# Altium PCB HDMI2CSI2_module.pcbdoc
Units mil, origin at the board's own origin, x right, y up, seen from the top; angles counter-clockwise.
Board outline 4345 x 2835 mil, 4 copper layers (Top Layer, Inner1, Inner2, Bottom Layer); 56 components, 47 nets, 282 pads, 152 vias.
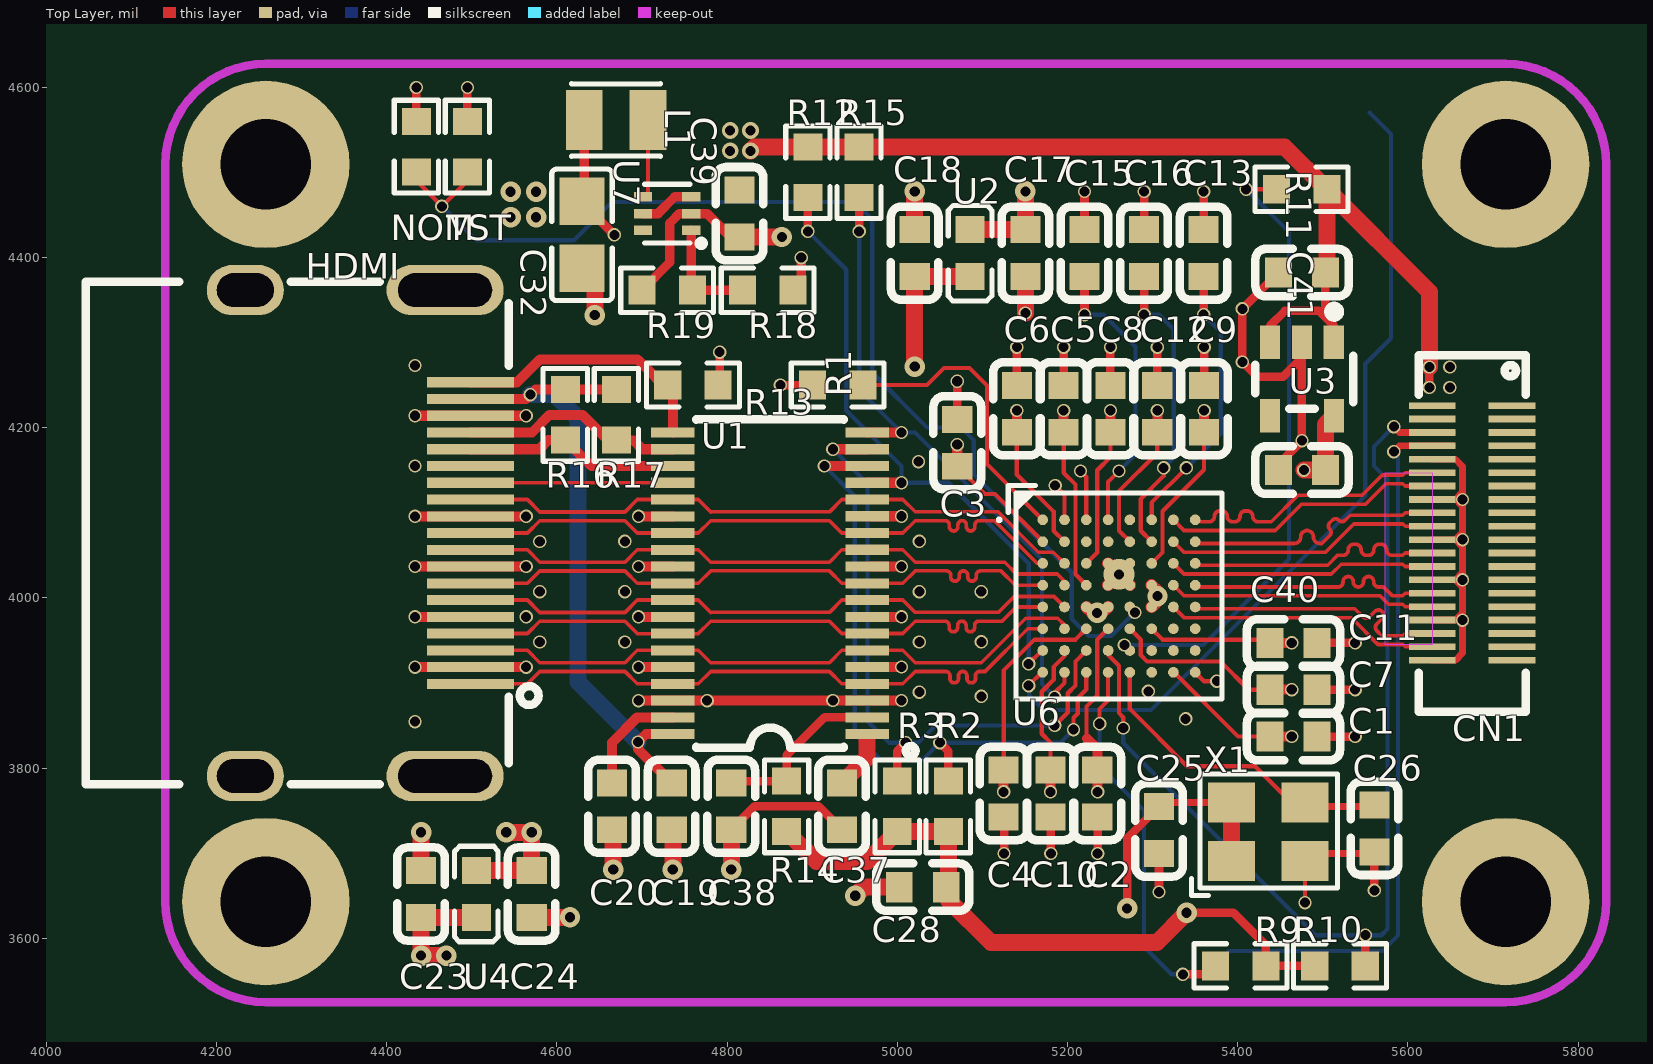
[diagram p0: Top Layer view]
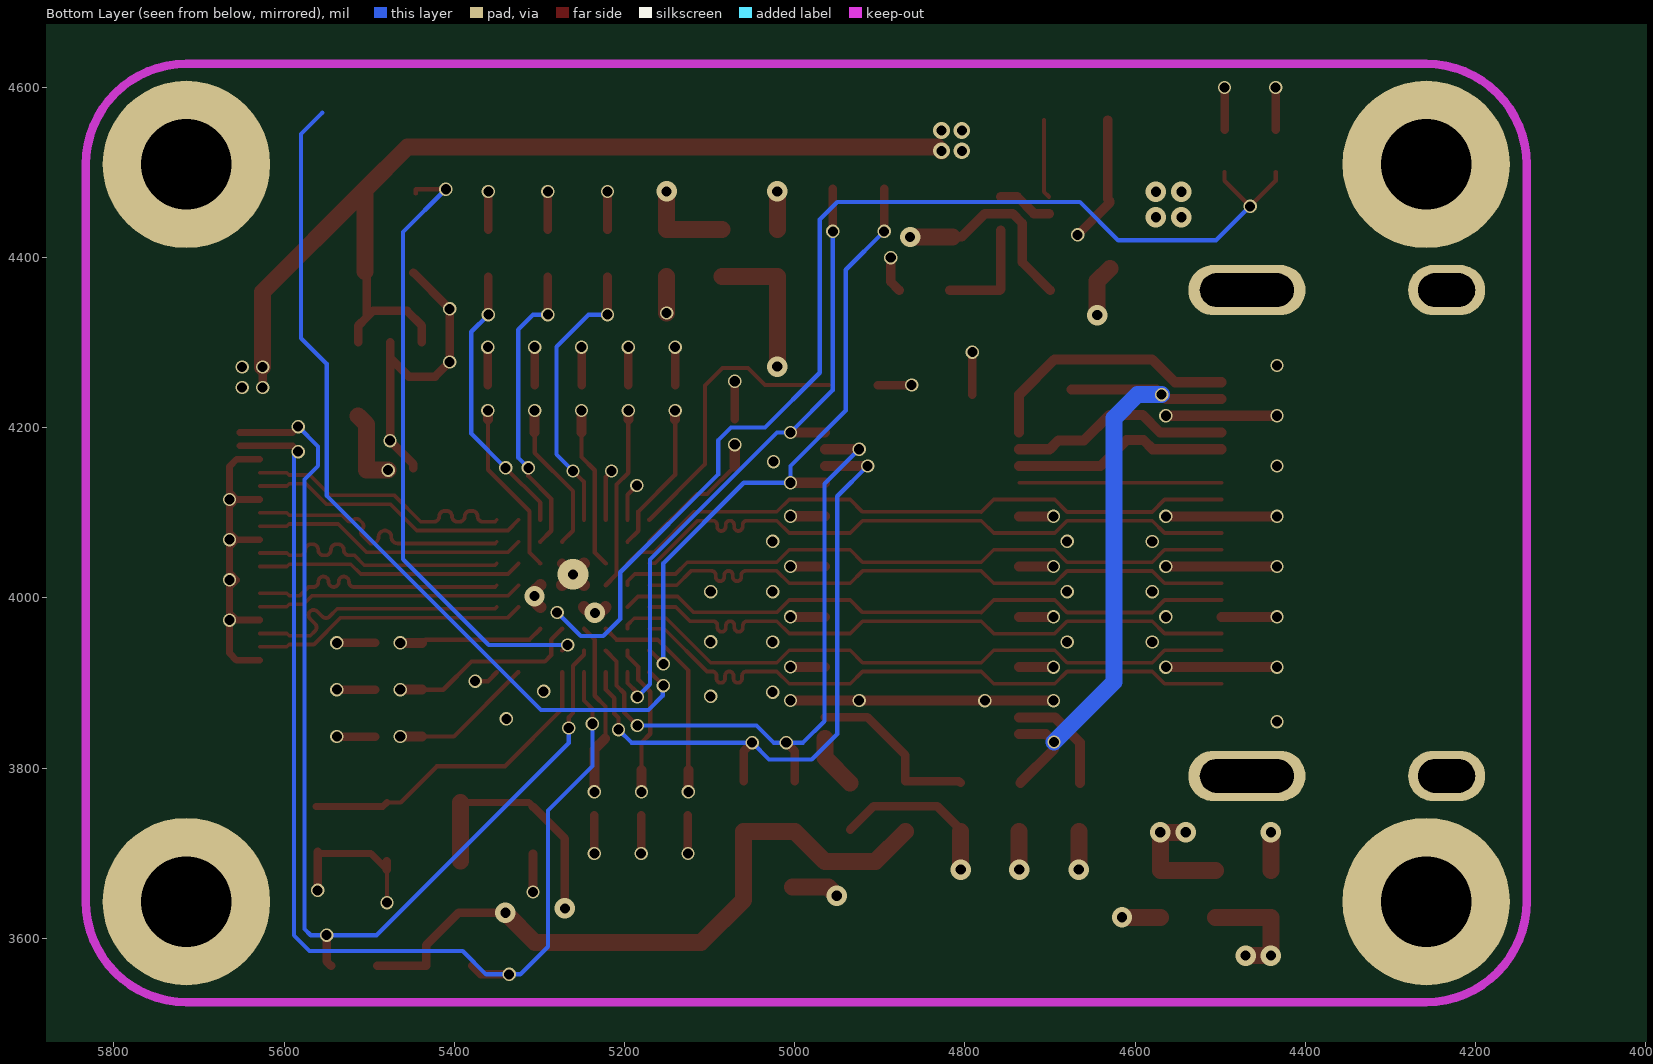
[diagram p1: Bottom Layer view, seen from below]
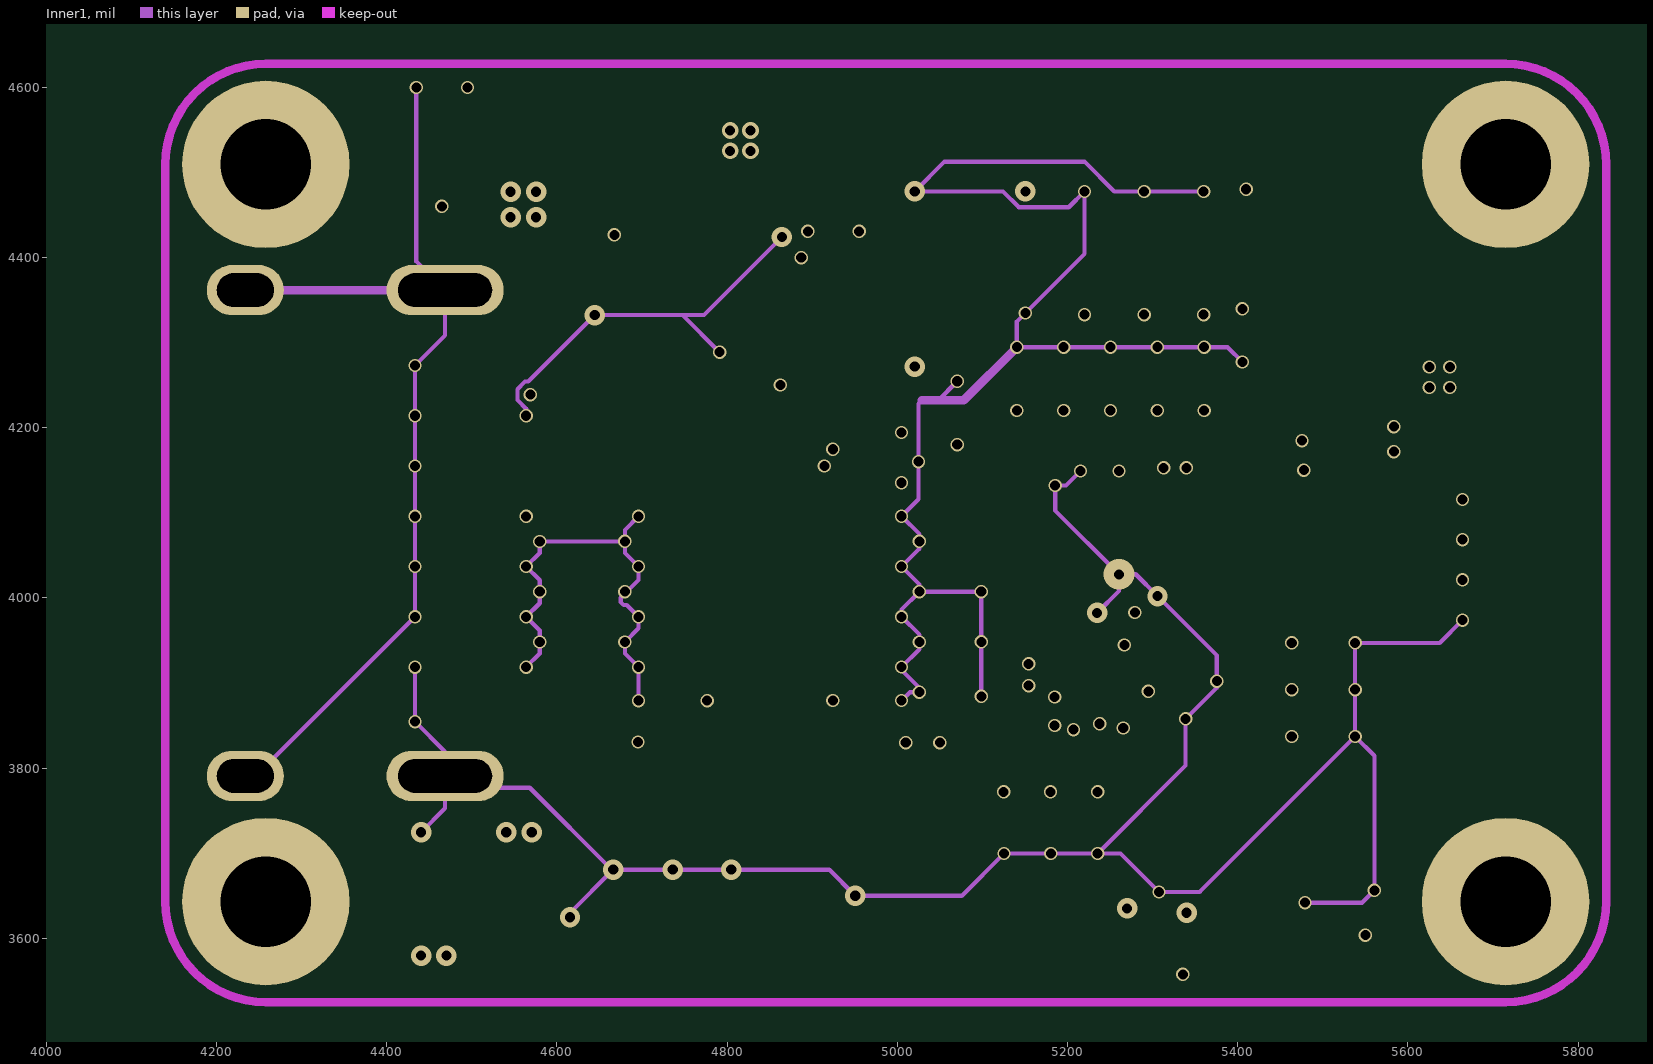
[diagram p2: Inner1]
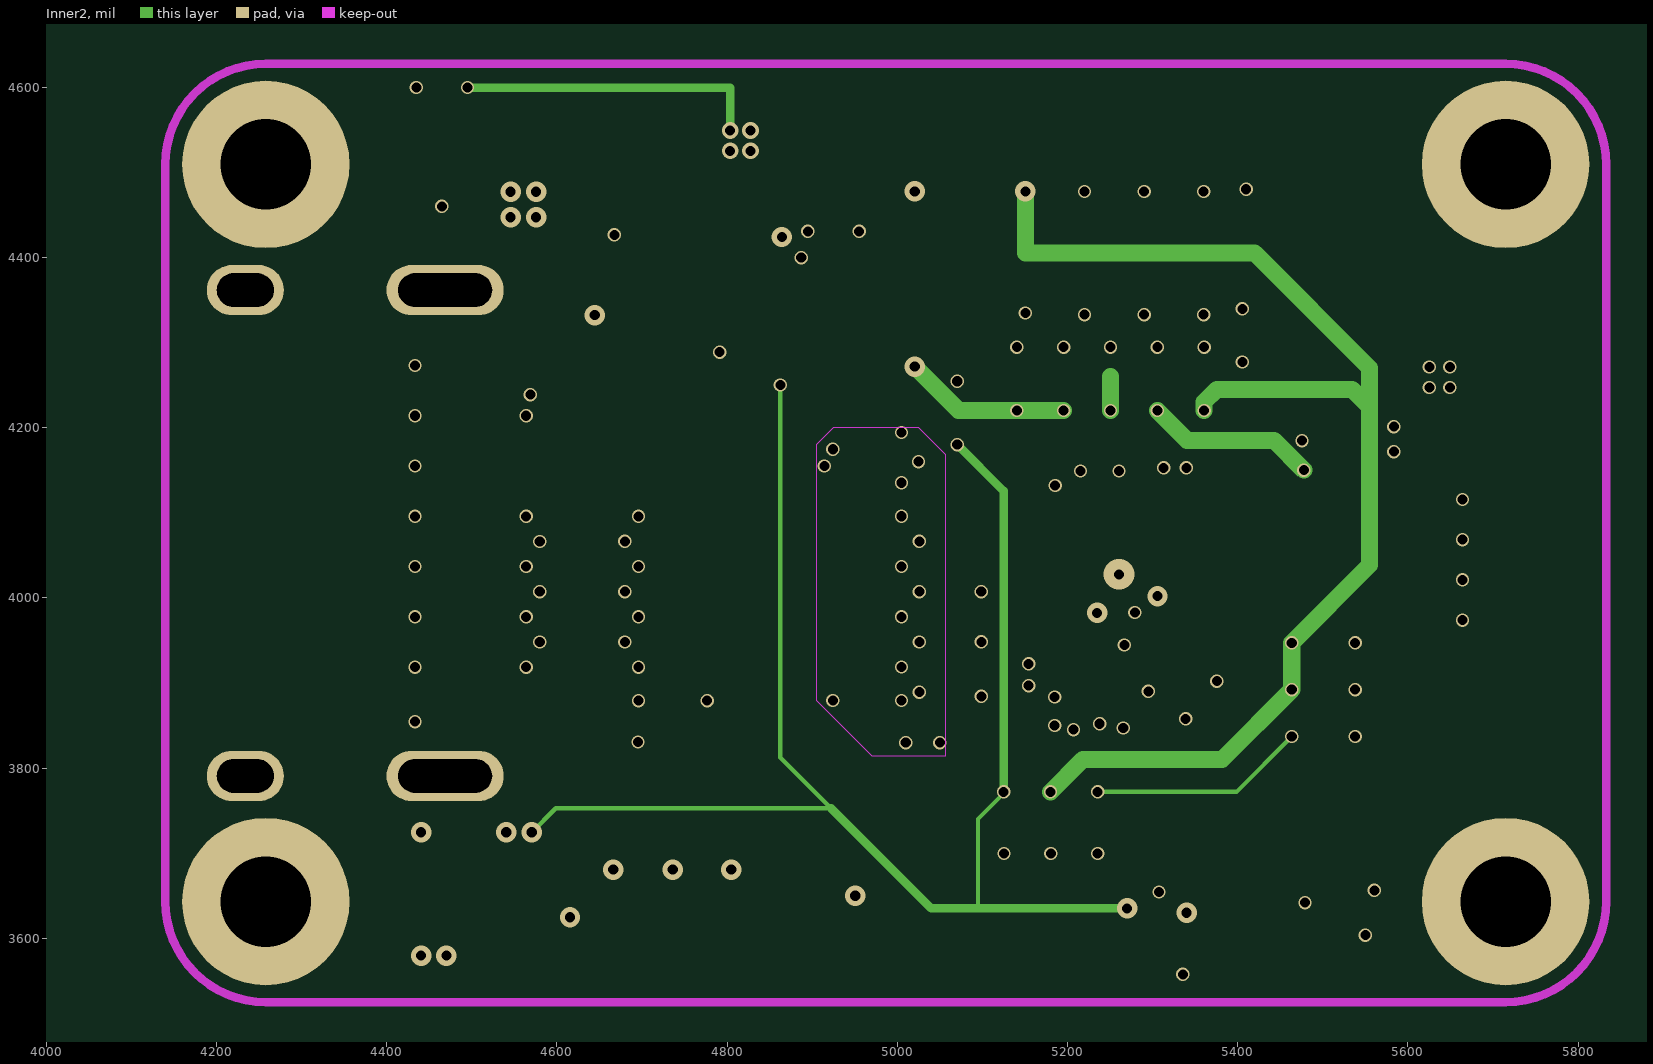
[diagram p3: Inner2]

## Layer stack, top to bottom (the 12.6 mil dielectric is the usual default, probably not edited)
Top Layer: signal copper (thickness not stored)
Dielectric: dielectric 12.6, FR-4, Dk 4.8
Inner1: signal copper (thickness not stored)
Dielectric: dielectric 12.6, FR-4, Dk 4.8
Inner2: signal copper (thickness not stored)
Dielectric: dielectric 12.6, FR-4, Dk 4.8
Bottom Layer: signal copper (thickness not stored)

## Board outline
7095,2750 2750,2750 2750,5585 7095,5585

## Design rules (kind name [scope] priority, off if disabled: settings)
BoardOutlineClearance copperThickness1oz [All] p0: genericclearance=10 ignorepadtopadclearanceinfootprint=FALSE except(0: Arc-SplitContinuation Track-SplitContinuation SMDPad-SplitContinuation THPad-SplitContinuation Via-SplitContinuation Fill-SplitContinuation Poly-SplitContinuation Region-SplitContinuation Text-SplitContinuation; 6: SMDPad-CutoutEdge THPad-CutoutEdge Via-CutoutEdge Fill-CutoutEdge Region-CutoutEdge; 11.8: Track-OutlineEdge SMDPad-OutlineEdge THPad-OutlineEdge Via-OutlineEdge Fill-OutlineEdge Region-OutlineEdge Poly-OutlineEdge Text-OutlineEdge Track-CutoutEdge)
BoardOutlineClearance copperThickness2oz [All] p0: genericclearance=10 ignorepadtopadclearanceinfootprint=FALSE except(0: Arc-SplitContinuation Track-SplitContinuation SMDPad-SplitContinuation THPad-SplitContinuation Via-SplitContinuation Fill-SplitContinuation Poly-SplitContinuation Region-SplitContinuation Text-SplitContinuation; 6: SMDPad-CutoutEdge THPad-CutoutEdge Via-CutoutEdge Fill-CutoutEdge Region-CutoutEdge; 11.8: Track-OutlineEdge SMDPad-OutlineEdge THPad-OutlineEdge Via-OutlineEdge Fill-OutlineEdge Region-OutlineEdge Poly-OutlineEdge Text-OutlineEdge Track-CutoutEdge)
BoardOutlineClearance copperThicknessInner0.5oz [All] p0: genericclearance=10 ignorepadtopadclearanceinfootprint=FALSE except(0: Arc-SplitContinuation Track-SplitContinuation SMDPad-SplitContinuation THPad-SplitContinuation Via-SplitContinuation Fill-SplitContinuation Poly-SplitContinuation Region-SplitContinuation Text-SplitContinuation; 6: SMDPad-CutoutEdge THPad-CutoutEdge Via-CutoutEdge Fill-CutoutEdge Region-CutoutEdge; 11.8: Track-OutlineEdge SMDPad-OutlineEdge THPad-OutlineEdge Via-OutlineEdge Fill-OutlineEdge Region-OutlineEdge Poly-OutlineEdge Text-OutlineEdge Track-CutoutEdge)
Clearance copperThickness1oz [(InNet('$1N490') OR InNet('$1N473') OR InNet('$1N491') OR InNet('3V3') OR InNet('1V2') OR InNet('2V5') OR InNet('GND') OR InNet('$1N487') OR InNet('$1N3181') OR InNet('A3V3') OR InNet('A1V2') OR InNet('HDMISDA') OR InNet('HDMISCL') OR InNet('HDMI2+') OR InNet('HDMI2-') OR InNet('HDMI1+') OR InNet('HDMI1-') OR InNet('HDMI0+') OR InNet('HDMI0-') OR InNet('HDMICLK+') OR InNet('HDMICLK-') OR InNet('HDMIHPD') OR InNet('HOST_SDA') OR InNet('HOST_SCL') OR InNet('HDMI5V') OR InNet('HDMICEC') OR InNet('$1N13322') OR InNet('CSID3P') OR InNet('CSID2P') OR InNet('CSICN') OR InNet('CSID1P') OR InNet('CSID0P') OR InNet('CSICP') OR InNet('CSID3N') OR InNet('CSID2N') OR InNet('CSID1N') OR InNet('CSID0N') OR InNet('HDMIHPD_OUT') OR InNet('HDMICEC_OUT') OR InNet('$1N17500') OR InNet('HDMISCL_OUT') OR InNet('HDMISDA_OUT') OR InNet('$1N18101') OR InNet('$1N18201') OR InNet('$1N17874') OR InNet('$1N34238') OR InNet('$1N34236'))] p1: gap=7 ignorepadtopadclearanceinfootprint=FALSE except(4: Track-Track Track-SMDPad SMDPad-SMDPad Track-Via SMDPad-Via THPad-Via Via-Via; 6: Track-THPad SMDPad-THPad THPad-THPad Track-Fill SMDPad-Fill THPad-Fill Via-Fill Fill-Fill SMDPad-Region THPad-Region Via-Region Fill-Region Region-Region Track-Poly SMDPad-Poly THPad-Poly Via-Poly Fill-Poly Poly-Poly Track-Text SMDPad-Text THPad-Text Via-Text Fill-Text Region-Text Poly-Text Text-Text; 6.9: Track-Hole SMDPad-Hole THPad-Hole Via-Hole Fill-Hole Region-Hole Poly-Hole Text-Hole Sheet-Hole; 11.8: Track-Region Region-Poly Track-Sheet SMDPad-Sheet THPad-Sheet Via-Sheet Fill-Sheet Region-Sheet Poly-Sheet Text-Sheet)
Clearance copperThickness2oz [All] p1: gap=7 ignorepadtopadclearanceinfootprint=FALSE except(6: Track-SMDPad SMDPad-SMDPad Track-THPad SMDPad-THPad THPad-THPad Track-Via SMDPad-Via THPad-Via Via-Via Track-Fill SMDPad-Fill THPad-Fill Via-Fill Fill-Fill SMDPad-Region THPad-Region Via-Region Fill-Region Region-Region Track-Poly SMDPad-Poly THPad-Poly Via-Poly Fill-Poly Poly-Poly Track-Text SMDPad-Text THPad-Text Via-Text Fill-Text Region-Text Poly-Text Text-Text; 6.9: Track-Hole SMDPad-Hole THPad-Hole Via-Hole Fill-Hole Region-Hole Poly-Hole Text-Hole Sheet-Hole; 8: Track-Track; 11.8: Track-Region Region-Poly Track-Sheet SMDPad-Sheet THPad-Sheet Via-Sheet Fill-Sheet Region-Sheet Poly-Sheet Text-Sheet)
Clearance copperThicknessInner0.5oz [All] p1: gap=7 ignorepadtopadclearanceinfootprint=FALSE except(3.5: Track-Track; 6: Track-SMDPad SMDPad-SMDPad Track-THPad SMDPad-THPad THPad-THPad Track-Via SMDPad-Via THPad-Via Via-Via Track-Fill SMDPad-Fill THPad-Fill Via-Fill Fill-Fill SMDPad-Region THPad-Region Via-Region Fill-Region Region-Region Track-Poly SMDPad-Poly THPad-Poly Via-Poly Fill-Poly Poly-Poly Track-Text SMDPad-Text THPad-Text Via-Text Fill-Text Region-Text Poly-Text Text-Text; 6.9: Track-Hole SMDPad-Hole THPad-Hole Via-Hole Fill-Hole Region-Hole Poly-Hole Text-Hole Sheet-Hole; 11.8: Track-Region Region-Poly Track-Sheet SMDPad-Sheet THPad-Sheet Via-Sheet Fill-Sheet Region-Sheet Poly-Sheet Text-Sheet)
DiffPairsRouting differentialPair [All] p1: maxuncoupledlength=10 minlimit=6 maxlimit=6 mostfreqgap=6 toplayer_minwidth=4.3 toplayer_prefwidth=4.3 toplayer_maxwidth=100 bottomlayer_minwidth=4.3 bottomlayer_prefwidth=4.3 bottomlayer_maxwidth=100 midlayer1_minwidth=4.3 midlayer1_prefwidth=4.3 midlayer1_maxwidth=100 midlayer2_minwidth=4.3 midlayer2_prefwidth=4.3 midlayer2_maxwidth=100
PasteMaskExpansion pasteMaskExpansion [All] p1: expansion=0
PlaneConnect innerPlane [All] p1: planeconnectstyle=Relief reliefexpansion=20 reliefentries=4 reliefconductorwidth=10 reliefairgap=10
PolygonConnect copperRegion [All] p1: connectstyle=Direct reliefentries=4 reliefconductorwidth=10 polygonreliefangle="90 Angle" airgapwidth=10
RoutingVias viaSize [All] p1: viastyle="Through Hole" holewidth=12 minholewidth=7.9 maxholewidth=248 width=24 minwidth=11.8 maxwidth=393.7
SolderMaskExpansion solderMaskExpansion [All] p1: useseparateexpansions=TRUE expansion=2 expansionbottom=2
Width copperThickness1oz [All] p1: maxlimit=100 minlimit=4 preferedwidth=10
Width copperThickness2oz [All] p1: maxlimit=100 minlimit=8 preferedwidth=10
Width copperThickness0.5oz [All] p1: maxlimit=100 minlimit=4 preferedwidth=10

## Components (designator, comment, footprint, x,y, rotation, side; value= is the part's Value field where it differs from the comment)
C1 "CGA0603X7R104K500JT" C0603 5465.5,3837 r180 top
C2 "CGA0603X7R104K500JT" C0603 5235,3770 r90 top
C3 "CGA0603X7R104K500JT" C0603 5070.5,4182 r270 top
C4 "CGA0603X7R104K500JT" C0603 5125,3770 r90 top
C5 "CGA0603X7R104K500JT" C0603 5195.5,4222 r270 top
C6 "CGA0603X7R104K500JT" C0603 5140.5,4222 r270 top
C7 "CGA0603X7R104K500JT" C0603 5465.5,3892 r180 top
C8 "CGA0603X7R104K500JT" C0603 5250.5,4222 r270 top
C9 "CGA0603X7R104K500JT" C0603 5360.5,4222 r270 top
C10 "CGA0603X7R104K500JT" C0603 5180,3770 r90 top
C11 "CGA0603X7R104K500JT" C0603 5465.5,3947 r180 top
C12 "CGA0603X7R104K500JT" C0603 5305.5,4222 r270 top
C13 "CGA0603X7R104K500JT" C0603 5360,4405 r90 top
C15 "CGA0603X7R104K500JT" C0603 5220,4405 r90 top
C16 "CGA0603X7R104K500JT" C0603 5290,4405 r90 top
C17 "CL10A105KB8NNNC" C0603 5150.5,4405 r90 top
C18 "CGA0603X7R104K500JT" C0603 5020.5,4405 r270 top
C19 "CGA0603X7R104K500JT" C0603 4735,3755 r90 top
C20 "CGA0603X7R104K500JT" C0603 4665,3755 r90 top
C23 "CL10A105KB8NNNC" C0603 4440.5,3652 r270 top
C24 "CGA0603X7R104K500JT" C0603 4570.5,3652 r90 top
C25 "CGA0603X7R104K500JT" C0603 5307.53,3727.09 r90 top
C26 "CL10C150JB8NNNC" C0603 5560.59,3729.03 r90 top
C28 "CGA0603X7R104K500JT" C0603 5030,3660 r0 top
C32 "CL21A226MAQNNNE" C0805 4629.61,4426.42 r90 top
C37 "CGA0603X7R104K500JT" C0603 4935,3755 r90 top
C38 "CGA0603X7R104K500JT" C0603 4805,3755 r90 top
C39 "CL10A105KB8NNNC" C0603 4814.61,4451.42 r90 top
C40 "CL10A105KB8NNNC" C0603 5475.5,4150 r0 top
C41 "CL10A105KB8NNNC" C0603 5475.5,4382 r0 top
CN1 "DF40C-40DS-0.4V(51)" CONN-SMD_DF40C-40DS-0.4V51 5675.43,4076.18 r90 top
HDMI "HDMI-001S" HDMI-SMD_HDMI-001S 4366.38,4076.08 r270 top
L1 "WPN252012H1R0MT" IND-SMD_L2.5-W2.0_WPN252012H 4669.61,4561.42 r180 top
NOM "0603WAF1002T5E" R0603 4435,4530 r90 top
R1 "0603WAF2001T5E" R0603 4930,4250 r180 top
R2 "0603WAF4702T5E" R0603 5060,3755 r90 top
R3 "0603WAF4702T5E" R0603 5000,3755 r90 top
R9 "0603WAF4701T5E" R0603 5403.38,3567.57 r180 top
R10 "0603WAF4701T5E" R0603 5520.18,3567.57 r0 top
R11 "0603WAF1002T5E" R0603 5475,4480 r180 top
R12 "0603WAF4702T5E" R0603 4895,4500 r270 top
R13 "0603WAF1002T5E" R0603 4760,4250 r180 top
R14 "0603WAF1002T5E" R0603 4870,3755 r270 top
R15 "0603WAF1003T5E" R0603 4955,4500 r270 top
R16 "M55342H12B1E70PT5" R0603 4610,4215 r270 top
R17 "M55342H12B1E70PT5" R0603 4670,4215 r270 top
R18 "Res_0603" R0603 4847.7,4361.43 r0 top
R19 "Res_0603" R0603 4729.61,4361.42 r0 top
TST "0603WAF1002T5E" R0603 4495,4530 r270 top
U1 "TPD12S521DBTR" TSSOP-38_L9.7-W4.4-P0.50-LS6.4-BL 4850.5,4017 r90 top
U2 "BLM18EG221SN1D" L0603 5085.5,4405 r270 top
U3 "TLV75725PDBVR" SOT-23-5_L2.9-W1.6-P0.95-LS2.8-BR 5475.5,4257 r90 top
U4 "BLM18EG221SN1D" L0603 4505.5,3652 r90 top
U6 "TC358743XBG" BGA-64_L6.0-W6.0-W8-R8-P0.65-D0.40-TL 5260.5,4002 r0 top
U7 "TLV62568ADRLR" SOT-563_L1.6-W1.2-P0.50-LS1.6-BL 4729.61,4451.42 r90 top
X1 "OT2EL4C4JI-111OLP-27M" OSC-SMD_4P-L3.2-W2.5-BL 5435.8,3725.15 r0 top

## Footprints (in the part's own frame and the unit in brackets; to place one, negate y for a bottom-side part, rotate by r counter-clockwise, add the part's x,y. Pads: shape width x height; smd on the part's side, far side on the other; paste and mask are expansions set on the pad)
BGA-64_L6.0-W6.0-W8-R8-P0.65-D0.40-TL [mm]
  round 0.32 smd: A1(-2.275,2.275) A2(-1.625,2.275) A3(-0.975,2.275) A4(-0.325,2.275) A5(0.325,2.275) A6(0.975,2.275) A7(1.625,2.275) A8(2.275,2.275) B1(-2.275,1.625) B2(-1.625,1.625) B3(-0.975,1.625) B4(-0.325,1.625) B5(0.325,1.625) B6(0.975,1.625) B7(1.625,1.625) B8(2.275,1.625) C1(-2.275,0.975) C2(-1.625,0.975) C3(-0.975,0.975) C4(-0.325,0.975) C5(0.325,0.975) C6(0.975,0.975) C7(1.625,0.975) C8(2.275,0.975) D1(-2.275,0.325) D2(-1.625,0.325) D3(-0.975,0.325) D4(-0.325,0.325) D5(0.325,0.325) D6(0.975,0.325) D7(1.625,0.325) D8(2.275,0.325) E1(-2.275,-0.325) E2(-1.625,-0.325) E3(-0.975,-0.325) E4(-0.325,-0.325) E5(0.325,-0.325) E6(0.975,-0.325) E7(1.625,-0.325) E8(2.275,-0.325) F1(-2.275,-0.975) F2(-1.625,-0.975) F3(-0.975,-0.975) F4(-0.325,-0.975) F5(0.325,-0.975) F6(0.975,-0.975) F7(1.625,-0.975) F8(2.275,-0.975) G1(-2.275,-1.625) G2(-1.625,-1.625) G3(-0.975,-1.625) G4(-0.325,-1.625) G5(0.325,-1.625) G6(0.975,-1.625) G7(1.625,-1.625) G8(2.275,-1.625) H1(-2.275,-2.275) H2(-1.625,-2.275) H3(-0.975,-2.275) H4(-0.325,-2.275) H5(0.325,-2.275) H6(0.975,-2.275) H7(1.625,-2.275) H8(2.275,-2.275)
  silkscreen extent -3.63,-3.08 3.08,3.3
C0603 [mm]
  rect 0.8x0.9 smd: 1(-0.7,0) 2(0.7,0)
  silkscreen extent -1.39,-0.71 1.39,0.71
C0805 [mm]
  rect 1.41x1.35 smd: 1(-1,0) 2(1,0)
  silkscreen extent -1.96,-0.9 1.96,0.9
CONN-SMD_DF40C-40DS-0.4V51 [mm]
  rect 0.2x1.4 smd: 1(3.8,-1.19) 2(3.8,1.19) 3(3.4,-1.19) 4(3.4,1.19) 5(3,-1.19) 6(3,1.19) 7(2.6,-1.19) 8(2.6,1.19) 9(2.2,-1.19) 10(2.2,1.19) 11(1.8,-1.19) 12(1.8,1.19) 13(1.4,-1.19) 14(1.4,1.19) 15(1,-1.19) 16(1,1.19) 17(0.6,-1.19) 18(0.6,1.19) 19(0.2,-1.19) 20(0.2,1.19) 21(-0.2,-1.19) 22(-0.2,1.19) 23(-0.6,-1.19) 24(-0.6,1.19) 25(-1,-1.19) 26(-1,1.19) 27(-1.4,-1.19) 28(-1.4,1.19) 29(-1.8,-1.19) 30(-1.8,1.19) 31(-2.2,-1.19) 32(-2.2,1.19) 33(-2.6,-1.19) 34(-2.6,1.19) 35(-3,-1.19) 36(-3,1.19) 37(-3.4,-1.19) 38(-3.4,1.19) 39(-3.8,-1.19) 40(-3.8,1.19)
  silkscreen extent -5.33,-1.6 5.3,1.6
HDMI-SMD_HDMI-001S [mm]
  rect 0.3x2.6 smd: 1(4.5,3.36) 2(4,3.36) 3(3.5,3.36) 4(3,3.36) 5(2.5,3.36) 6(2,3.36) 7(1.5,3.36) 8(1,3.36) 9(0.5,3.36) 10(0,3.36) 11(-0.5,3.36) 12(-1,3.36) 13(-1.5,3.36) 14(-2,3.36) 15(-2.5,3.36) 16(-3,3.36) 17(-3.5,3.36) 18(-4,3.36) 19(-4.5,3.36)
  oval 1.5x3.5 hole 1 slot 2.8 at 90 deg: 20(-7.25,2.6) 21(7.25,2.6)
  oval 1.5x2.3 hole 1 slot 1.7 at 90 deg: 22(-7.25,-3.36) 23(7.25,-3.36)
  silkscreen extent -7.5,-8.12 7.5,5.39
IND-SMD_L2.5-W2.0_WPN252012H [mm]
  rect 1.1x1.8 smd: 1(-0.95,0) 2(0.95,0)
  silkscreen extent -1.33,-1.09 1.33,1.09
L0603 [mm]
  rect 0.8x0.864 smd: 1(-0.7,0) 2(0.7,0)
  silkscreen extent -1.42,-0.65 1.42,0.65
OSC-SMD_4P-L3.2-W2.5-BL [mm]
  rect 1.4x1.2 smd: 1(-1.1,-0.875) 2(1.1,-0.875) 3(1.1,0.875) 4(-1.1,0.875)
  silkscreen extent -2.29,-1.9 2.07,1.72
R0603 [mil]
  rect 31.75x34.02 smd: 1(-29.66,0) 2(29.66,0)
  silkscreen extent -55,-26 55,26
SOT-23-5_L2.9-W1.6-P0.95-LS2.8-BR [mm]
  rect 1x0.6 smd: 1(1.1,-0.95) 2(1.1,0) 3(1.1,0.95) 4(-1.1,0.95) 5(-1.1,-0.95)
  silkscreen extent -0.89,-1.52 2.16,1.4
SOT-563_L1.6-W1.2-P0.50-LS1.6-BL [mm]
  rect 0.28x0.545 smd: 1(-0.5,-0.723) 2(0,-0.723) 3(0.5,-0.723) 4(0.5,0.723) 5(0,0.723) 6(-0.5,0.723)
  silkscreen extent -0.99,-1.12 0.88,0.68
TSSOP-38_L9.7-W4.4-P0.50-LS6.4-BL [mm]
  rect 0.3x1.3 smd: 1(-4.501,-2.899) 2(-3.999,-2.901) 3(-3.498,-2.901) 4(-2.999,-2.901) 5(-2.499,-2.901) 6(-1.999,-2.901) 7(-1.499,-2.901) 8(-0.999,-2.901) 9(-0.499,-2.901) 10(0.001,-2.901) 11(0.501,-2.901) 12(1.001,-2.901) 13(1.501,-2.901) 14(2.001,-2.901) 15(2.501,-2.901) 16(3.001,-2.901) 17(3.501,-2.901) 18(4.001,-2.901) 19(4.501,-2.901) 20(4.5,2.899) 21(4.001,2.9) 22(3.501,2.899) 23(3.002,2.899) 24(2.499,2.901) 25(2,2.9) 26(1.5,2.9) 27(1,2.9) 28(0.5,2.9) 29(0,2.9) 30(-0.5,2.9) 31(-1,2.9) 32(-1.5,2.9) 33(-2,2.9) 34(-2.5,2.9) 35(-3,2.9) 36(-3.5,2.9) 37(-4,2.9) 38(-4.5,2.9)
  silkscreen extent -5.14,-4.34 4.9,2.2

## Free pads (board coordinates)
  round 196.85 hole 106.3: 1(4258.11,3643.11) 1(4258.11,4509.25) 1(5714.8,3643.11) 1(5714.8,4509.25)

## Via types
v1: diameter 15.7, hole 11.8, Top Layer to Bottom Layer, 124 vias
v2: diameter 24, hole 12, Top Layer to Bottom Layer, 21 vias
v3: diameter 19.7, hole 11.8, Top Layer to Bottom Layer, 4 vias
v4: diameter 24, hole 11.8, Top Layer to Bottom Layer, 2 vias
v5: diameter 36, hole 11.8, Top Layer to Bottom Layer, 1 vias

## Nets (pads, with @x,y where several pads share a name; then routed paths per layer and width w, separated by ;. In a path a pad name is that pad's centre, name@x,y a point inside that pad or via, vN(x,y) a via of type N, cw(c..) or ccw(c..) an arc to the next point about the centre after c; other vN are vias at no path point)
1V2: C7.2 C8.2 C9.2 C10.2 C11.2 C17.2 C32.2 L1.2 R18.2 U2.1 U6.C3 U6.C6 U6.F5 U6.F6 U6.G2 | length 2825
  Top Layer w5: C10.2 5180,3830 5169.69,3840.31 5169.69,3889.69 5183.73,3903.73 5183.73,3918.73 5196.52,3931.52 U6.G2 ; U6.C3 5234.91,4053.19 5234.91,4149.91 5250.5,4165.5 C8.2 ; U6.F5 5286.09,3950.82 5286.09,3932.72 5293.59,3925.22 5379.77,3925.23 5413,3892 C7.2 ; U6.F6 5311.68,3950.82 5434.12,3950.82 C11.2 ; U6.C6 5311.69,4053.19 5311.69,4101.69 5360.5,4150.5 C9.2@5360.5,4209.44
  Top Layer w11: L1.2 4632.21,4468.39 C32.2 4629.61,4464.38 v1(4667.57,4426.42) ; R18.2 4887.2,4371.27 v1(4887.2,4399.55)
  Top Layer w11.8: v1(5180,3772) C10.2 ; C8.2 v1(5250.5,4220) ; C9.2@5360.5,4209.44 v1(5360.5,4220) ; C7.2 v1(5463.5,3892) ; C11.2 v1(5463.5,3947)
  Top Layer w20: U2.1 C17.2 v2(5150.51,4477.42)
  Inner2 w20: v2(5150.51,4477.42) 5150.51,4405 5420,4405 5555,4270 5555,4224.14 ; v1(5180,3772) 5218,3810 5381.5,3810 v1(5463.5,3892) v1(5463.5,3947) 5555,4038.5 5555,4224.14 ; v1(5250.5,4220) 5250.5,4260 ; v1(5360.5,4220) 5360.5,4230 5375.5,4245 5534.14,4245 5555,4224.14
  other v2: 4545.7,4447.13 4575.7,4447.13 4545.7,4477.13 4575.7,4477.13
2V5: C12.2 C40.2 U3.5 U6.B5 | length 472.4
  Top Layer w5: U6.B5 5260.5,4078.78 5260.5,4125.27 5305.5,4170.27 C12.2
  Top Layer w11.8: C12.2 v1(5305.5,4220)
  Top Layer w20: v1(5477.69,4149.88) 5502.94,4149.88 C40.2 5503.06,4203.84 U3.5
  Inner2 w20: v1(5305.5,4220) 5340.5,4185 5442.57,4185 v1(5477.69,4149.88)
3V3: C1.2 C2.2 C23.2 C28.2 C39.2 C41.2 CN1.2 CN1.4 R2.1 R3.1 R9.1 R10.1 R11.1 R12.1 R14.2 R15.1 TST.1 U3.1 U3.3 U4.1 U6.F4 U6.H7 U7.3 U7.5 | length 3312.2
  Top Layer w5: 5222.4,3835.1 5222.4,3872.4 5234.9,3884.9 5234.9,3950.81 U6.F4 ; U6.H7 5325.07,3912.43 5400.5,3837 C1.2
  Top Layer w10: TST.1@4495,4549.69 v1(4495,4599.53) ; v2(5340,3630) 5395,3630 5433.04,3591.96 R9.1 R10.1 ; U3.3 5438.11,4319.61 5455.5,4337 5495.5,4337 5503.06,4329.44 ; C41.2@5504.66,4383.6 C41.2 5503.06,4329.44 ; U3.1 5512.9,4319.6 5503.06,4329.44 ; v1(5625.24,4247.14) v1(5625.24,4271.14)
  Top Layer w11: U7.5 4718.98,4451.41 4738.67,4471.1 U7.3
  Top Layer w11.8: 5223.02,3834.48 5235.5,3822 v1(5235.5,3772) ; C1.2 v1(5463.5,3837)
  Top Layer w20: v2(4440.49,3579.58) v2(4470.35,3579.57) ; v2(4440.49,3579.58) C23.2 U4.1 ; v3(4827.7,4525.13) 4832.23,4529.66 R12.1 R15.1 5455,4529.66 R11.1 ; R14.2 4905.34,3690 4964.66,3690 R3.1 R2.1 5060,3645 5110,3595 5305,3595 v2(5340,3630) ; C41.2@5504.66,4383.6 R11.1 ; v1(5625.24,4271.14) 5625.24,4359.42 R11.1
  Inner2 w5: v1(5235.5,3772) 5398.5,3772 v1(5463.5,3837)
  Inner2 w10: v1(4495,4599.53) 4803.7,4599.53 v3(4803.7,4549.13)
  other v1: 5649.24,4247.14 5649.24,4271.14
  other v3: 4803.7,4525.13 4827.7,4549.13
$1N473: C16.1 U6.B6 | length 357.6
  Top Layer w5: U6.B6 5286.09,4078.78 5286.09,4116.09 5312.97,4142.97 v1(5312.97,4152.66)
  Top Layer w10: v1(5289.99,4332.58) C16.1
  Bottom Layer w5: v1(5289.99,4332.58) 5307.42,4332.58 5325,4315 5325,4164.69 v1(5312.97,4152.66)
$1N487: R1.1 U6.A1 | length 347.6
  Top Layer w5: R1.1 5035,4250 5055,4270 5085,4270 5105.5,4249.5 5105.5,4157 U6.A1
$1N490: C13.1 U6.A6 | length 327.7
  Top Layer w5: U6.A6 5298.89,4111.8 v1(5339.74,4152.66)
  Top Layer w10: v1(5359.99,4332.58) C13.1
  Bottom Layer w5: v1(5339.74,4152.66) 5380,4192.91 5380,4312.57 v1(5359.99,4332.58)
$1N491: C15.1 U6.A4 | length 337.2
  Top Layer w5: U6.A4 5247.7,4136.24 v1(5260.5,4149.05)
  Top Layer w10: v1(5219.99,4332.58) C15.1
  Bottom Layer w5: v1(5219.99,4332.58) 5242.42,4332.58 5280,4295 5280,4168.54 v1(5260.5,4149.05)
$1N3181: NOM.1 TST.2 U6.E5 | length 1338.7
  Top Layer w5: NOM.1 4435,4490 v1(4465,4460) 4495,4490 TST.2
  Bottom Layer w5: v1(4465,4460) 4505,4420 4620,4420 4665,4465 4950,4465 4970.58,4444.42 4970.58,4264.42 5035,4200 5075,4200 5090,4185 5090,4145 5205,4030 5205,3975 5225,3955 5251.39,3955 v1(5279.1,3982.71)
$1N13322: C26.2 U6.H5 X1.3 | length 379.9
  Top Layer w5: U6.H5 5273.3,3869.2 5340.5,3802 5420.5,3802 5462.9,3759.6 X1.3
  Top Layer w8: X1.3 5484.05,3754.65 C26.2@5562.53,3754.65
$1N17500: C20.2 U1.37 | length 131
  Top Layer w11.8: C20.2 4665,3830 4694.52,3859.53 U1.37
$1N17874: R11.2 U6.G5 | length 740
  Top Layer w5: v1(5266.8,3944.51) U6.G5 ; v1(5410,4480) 5445,4480 5445.34,4479.66 R11.2@5445.34,4475
  Bottom Layer w5: v1(5266.8,3944.51) 5359.51,3944.51 5460.21,4045.21 5460.21,4429.79 v1(5410,4480)
$1N18101: C37.2 U1.1 | length 64.6
  Top Layer w20: C37.2 4964.59,3812.15 U1.1@4964.59,3834.94
$1N18201: C38.2 R14.1 U1.2 | length 209.4
  Top Layer w10: C38.2 4807.1,3784.66 R14.1 4870,3815 4914.56,3859.57 U1.2
$1N34236: R18.1 R19.2 U7.1 | length 129.6
  Top Layer w11: U7.1 4758.06,4362.64 R19.2 R18.1
$1N34238: L1.1 U7.4 | length 92.7
  Top Layer w5: U7.4 4707.01,4476.95 L1.1
A1V2: C5.2 C6.2 C18.2 U2.2 U6.B2 U6.D3 | length 760.6
  Top Layer w5: C6.2@5140.5,4209.44 5140.5,4144.5 5183.72,4101.28 5183.72,4078.78 U6.B2 ; C5.2@5195.5,4209.44 5195.5,4147 5209.32,4133.18 5209.32,4027.59 U6.D3
  Top Layer w11.8: C6.2@5140.5,4209.44 v1(5140.5,4220) ; C5.2@5195.5,4209.44 v1(5195.5,4220)
  Top Layer w20: v2(5020.5,4271.66) C18.2 U2.2
  Inner2 w20: v2(5020.5,4271.66) 5072.16,4220 v1(5140.5,4220) v1(5195.5,4220)
A3V3: C3.2 C4.2 C24.2 C25.2 R1.2 U4.2 U6.B1 U6.F3 X1.1 X1.4 | length 2753.5
  Top Layer w5: C3.2 5102.94,4122 5114.91,4122 U6.B1 ; C4.2 5125,3914.68 5161.14,3950.82 5209.32,3950.82 U6.F3
  Top Layer w8: C25.2 5312.47,3759.6 X1.4
  Top Layer w10: v1(4862.59,4250) R1.2@4902.44,4250 ; v2(5270,3635) 5270,3717.12 C25.2
  Top Layer w11.8: C3.2 v1(5070.5,4180) ; v1(5125,3772) C4.2
  Top Layer w20: U4.2 C24.2 v2(4570.51,3724.42) ; v2(4540.65,3724.43) v2(4570.51,3724.42) ; X1.1 X1.4
  Inner2 w5: v2(4570.51,3724.42) 4598.81,3752.72 4922.28,3752.72 4862.59,3812.41 v1(4862.59,4250) ; 5094.62,3635 5095,3635.38 5095,3740 v1@5125,3770
  Inner2 w10: 4922.28,3752.72 5040,3635 5094.62,3635 v2(5270,3635) ; v1(5070.5,4180) 5125,4125.5 v1(5125,3772)
CSICN: CN1.26 U6.C7 | length 315.2
  Top Layer w4.3: U6.C7 5336.93,4027.94 5509.94,4027.94 5521.53,4039.53 5594,4039.53 5596.72,4036.81 CN1.26
CSICP: CN1.24 U6.C8 | length 315.4
  Top Layer w4.3: U6.C8 5352.22,4038.24 5505.67,4038.24 5517.27,4049.83 5523.35,4049.83 ccw(c5523.35,4056.42) 5529.93,4056.42 cw(c5536.52,4056.42) 5536.52,4063 5538.35,4063 cw(c5538.35,4056.42) 5544.93,4056.42 ccw(c5551.52,4056.42) 5551.52,4049.83 5553.35,4049.83 ccw(c5553.35,4056.42) 5559.93,4056.42 cw(c5566.52,4056.42) 5566.52,4063 5568.35,4063 cw(c5568.35,4056.42) 5574.93,4056.42 ccw(c5581.52,4056.42) 5581.52,4049.83 5594,4049.83 5596.72,4052.56 CN1.24
CSID0N: CN1.38 U6.E7 | length 323.5
  Top Layer w4.3: U6.E7 5336.93,3976.75 5533.25,3976.75 5564.95,3945.05 5594,3945.05 5596.72,3942.33 CN1.38
CSID0P: CN1.36 U6.E8 | length 324.3
  Top Layer w4.3: U6.E8 5352.22,3987.05 5537.52,3987.05 5546.57,3978 ccw(c5550.81,3982.24) 5555.05,3978 5561.05,3983.99 cw(c5565.29,3979.75) 5569.53,3975.5 5563.54,3969.51 ccw(c5567.78,3965.27) 5563.54,3961.03 5569.22,3955.35 5594,3955.35 5596.72,3958.07 CN1.36
CSID1N: CN1.32 U6.D7 | length 314.6
  Top Layer w4.3: U6.D7 5336.93,4002.35 5567.09,4002.35 5577.14,3992.29 5594,3992.29 5596.72,3989.57 CN1.32
CSID1P: CN1.30 U6.D8 | length 313.3
  Top Layer w4.3: U6.D8 5352.22,4012.65 5517.74,4012.65 ccw(c5517.74,4018.65) 5523.74,4018.65 5523.74,4018.95 cw(c5529.74,4018.95) 5535.74,4018.95 5535.74,4018.65 ccw(c5541.74,4018.65) 5547.74,4018.65 5547.74,4018.95 cw(c5553.74,4018.95) 5559.74,4018.95 5559.74,4018.65 ccw(c5565.74,4018.65) 5565.74,4012.65 5571.35,4012.65 5581.41,4002.59 5594,4002.59 5596.72,4005.32 CN1.30
CSID2N: CN1.20 U6.B7 | length 324.2
  Top Layer w4.3: U6.B7 5336.93,4053.53 5503.1,4053.53 5536.35,4086.78 5594,4086.78 5596.72,4084.06 CN1.20
CSID2P: CN1.18 U6.B8 | length 323.9
  Top Layer w4.3: U6.B8 5352.22,4063.83 5466.51,4063.83 ccw(c5466.51,4071.33) 5474.01,4071.33 5474.01,4071.5 cw(c5481.51,4071.5) 5489.01,4071.5 5489.01,4071.33 ccw(c5496.51,4071.33) 5496.51,4063.83 5498.83,4063.83 5508.08,4073.08 ccw(c5504.33,4076.83) 5508.08,4080.58 cw(c5511.83,4084.33) 5508.08,4088.08 5511.19,4091.19 cw(c5514.94,4087.44) 5518.69,4091.19 ccw(c5522.44,4094.94) 5526.19,4091.19 5532.08,4097.08 5594,4097.08 5596.72,4099.81 CN1.18
CSID3N: CN1.14 U6.A7 | length 333.1
  Top Layer w4.3: U6.A7 5336.93,4079.12 5444.12,4079.12 5475,4110 5550.15,4110 5574.17,4134.02 5594,4134.02 5596.72,4131.3 CN1.14
CSID3P: CN1.12 U6.A8 | length 332
  Top Layer w4.3: U6.A8 5352.22,4089.42 5366.4,4089.42 ccw(c5366.4,4095.71) 5372.69,4095.71 cw(c5378.98,4095.71) 5378.98,4102 5381.4,4102 cw(c5381.4,4095.71) 5387.69,4095.71 ccw(c5393.98,4095.71) 5393.98,4089.42 5396.4,4089.42 ccw(c5396.4,4095.71) 5402.69,4095.71 cw(c5408.98,4095.71) 5408.98,4102 5411.4,4102 cw(c5411.4,4095.71) 5417.69,4095.71 ccw(c5423.98,4095.71) 5423.98,4089.42 5439.42,4089.42 5470.3,4120.3 5545.88,4120.3 5569.9,4144.32 5594,4144.32 5596.72,4147.05 CN1.12
GND: C1.1 C2.1 C3.1 C4.1 C5.1 C6.1 C7.1 C8.1 C9.1 C10.1 C11.1 C12.1 C13.2 C15.2 C16.2 C17.1 C18.1 C19.1 C20.1 C23.1 C24.1 C25.1 C26.1 C28.1 C32.1 C37.1 C38.1 C39.1 C40.1 C41.1 CN1.10 CN1.16 CN1.22 CN1.28 CN1.34 CN1.40 HDMI.2 HDMI.5 HDMI.8 HDMI.11 HDMI.17 HDMI.20 HDMI.21 HDMI.22 HDMI.23 NOM.2 R13.1 R19.1 U1.3 U1.5 U1.8 U1.11 U1.14 U1.25 U1.28 U1.31 U1.34 U1.36 U3.2 U6.A2 U6.A3 U6.C4 U6.C5 U6.D4 U6.D5 U6.D6 U6.E3 U6.E4 U6.E6 U6.H8 U7.2 X1.2 | length 10873.4
  Top Layer w5: v1(5185.5,4132) 5196.52,4120.98 U6.A2 ; v1(5215.21,4148.92) 5222.11,4142.03 U6.A3 ; U6.H8 5360.5,3902 v1(5375.5,3902) ; v1(5479.11,3641.76) X1.2@5479.11,3680.6
  Top Layer w8: X1.2@5479.11,3680.6 5498.04,3699.53 C26.1@5560.59,3699.53 ; CN1.40 5655.64,3926.58 5664.14,3935.08 v1(5664.14,3973.81) ; CN1.34 5655.64,3973.81 5664.14,3982.31 5664.14,4012.56 5655.64,4021.06 5664.14,4029.56 5664.14,4059.81 CN1.22@5655.65,4068.3 ; CN1.22 CN1.22@5655.64,4068.31 ; CN1.16 5655.64,4115.55 5664.14,4124.05 5664.14,4154.3 5655.64,4162.8 CN1.10 ; v1@5659.89,4111.3 5664.14,4107.05 5664.14,4076.8 CN1.22@5655.65,4068.3
  Top Layer w10: NOM.2@4435,4549.69 v1(4435,4599.53) ; R13.1@4791.3,4238.68 v1(4791.3,4288.53) ; C38.1 4832.56,3755 4907.44,3755 C37.1 ; C3.1 v1(5070.5,4254.41) ; v1(5125.49,3699.58) C4.1@5125.5,3744.44 ; C6.1 v1(5140.51,4294.42) ; v1(5180.49,3699.58) C10.1@5180.5,3744.44 ; C5.1 v1(5195.51,4294.42) ; C15.2 v1(5220.01,4477.43) ; v1(5235.49,3699.58) C2.1@5235.5,3744.44 ; C8.1 v1(5250.51,4294.42) ; C16.2 v1(5290.01,4477.43) ; C12.1 v1(5305.51,4294.42) ; v1(5307.52,3654.37) C25.1 ; C13.2 v1(5360.01,4477.42) ; C9.1 v1(5360.51,4294.42) ; C40.1@5447.94,4152 5447.94,4157 v1(5475.51,4184.56) U3.2@5475.51,4282.01 ; C41.1 v1(5405.5,4339.55) v1(5405.5,4277) 5422.57,4259.93 5453.43,4259.93 U3.2@5475.51,4282.01 ; U3.2 U3.2@5475.51,4282.01 ; X1.2@5479.11,3680.6 X1.2 ; C1.1 v1(5537.92,3836.99) ; C7.1 v1(5537.92,3891.99) ; C11.1 v1(5537.92,3946.99) ; v1(5560.58,3656.31) 5560.59,3699.53 C26.1
  Top Layer w11: R19.1 4732.7,4394.17 4732.7,4440.13 4743.98,4451.41 U7.2 4776.42,4451.41 4803.97,4423.86 C39.1
  Top Layer w11.8: v1(4433.34,3918.6) HDMI.2 v1(4563.98,3918.6) ; v1(4433.34,3977.65) HDMI.5 ; v1(4433.34,4036.71) HDMI.8 v1(4563.98,4036.71) ; v1(4433.34,4095.76) HDMI.11 v1(4563.98,4095.76) ; v1(4433.34,4213.88) HDMI.17 v1(4563.98,4213.88) ; v1(4696.01,3879.22) U1.36 v1(4776.66,3879.22) v1@4924.33,3879.22 ; v1(4696.01,3918.59) U1.34 ; v1(4696.01,3977.64) U1.31 ; v1(4696.01,4036.7) U1.28 ; v1(4696.01,4095.74) U1.25 ; v1(4924.39,3879.28) U1.3 v1(5005.04,3879.28) ; U1.5 v1(5005.04,3918.62) ; U1.8 v1(5005.04,3977.68) ; U1.11 v1(5005.04,4036.74) ; U1.14 v1(5005.04,4095.78) ; v5(5260.5,4027.6) U6.C5
  Top Layer w14: U6.E3 5228.96,3982.35 v4(5234.9,3982.35) 5240.85,3982.35 U6.E4 ; U6.D4 v5(5260.5,4027.6) ; U6.C4 v5(5260.5,4027.6) ; U6.D5 v5(5260.5,4027.6) ; U6.E6 5305.74,3996.05 v4(5305.74,4002) 5305.74,4007.95 U6.D6
  Top Layer w20: C23.1 v2(4440.51,3724.42) ; C24.1 4570.64,3624.58 v2(4615.49,3624.58) ; C32.1 4644.61,4372.05 v2(4644.61,4332.2) ; v2(4666.29,3680.61) C20.1@4666.3,3725.47 ; v2(4736.29,3680.61) C19.1@4736.3,3725.47 ; v2(4804.99,3680.61) C38.1@4805,3725.47 ; C39.1 v2(4864.46,4423.86) ; v2(4950.62,3650) 4960.62,3660 C28.1 ; C18.1 v2(5020.51,4477.42) ; v1(5150.5,4334.59) C17.1
  Inner1 w5: HDMI.23 4246.33,3790.64 v1(4433.34,3977.65) v1(4433.34,4036.71) v1(4433.34,4095.76) v1(4433.34,4154.82) v1(4433.34,4213.88) v1(4433.34,4272.93) 4468.74,4308.33 HDMI.20 4435,4395.26 v1(4435,4599.53) ; v1(4433.34,3918.6) v1(4433.34,3854.54) 4468.74,3819.14 HDMI.21 ; v2(4440.51,3724.42) 4468.74,3752.65 HDMI.21 ; v1(4563.98,3918.6) 4579.98,3934.6 v1(4579.98,3948.1) 4579.98,3961.66 v1(4563.98,3977.65) 4579.98,3993.65 v1(4579.98,4007.15) 4579.98,4020.71 v1(4563.98,4036.71) 4579.98,4052.71 v1(4579.98,4066.21) v1(4680.02,4066.25) ; v1(4563.98,4213.88) 4563.98,4222.06 4553.68,4232.36 4553.68,4245.04 4562.65,4254 4566.41,4254 v2(4644.61,4332.2) 4747.63,4332.2 ; v2(4615.49,3624.58) 4615.49,3629.81 v2(4666.29,3680.61) ; v1(4696.01,3879.22) v1(4696.01,3918.59) 4680.02,3934.58 v1(4680.02,3948.14) 4696.01,3964.14 v1(4696.01,3977.64) 4682.18,3991.46 4678.54,3991.46 4675,3995 4675,4000 4696.01,4021.01 v1(4696.01,4036.7) 4680.02,4052.69 v1(4680.02,4066.25) 4680.02,4079.75 v1(4696.01,4095.74) ; v1(4791.3,4288.53) 4747.63,4332.2 ; v2(4864.46,4423.86) 4772.8,4332.2 4747.63,4332.2 ; v1(5005.04,3879.28) 5014.83,3889.07 v1(5026.03,3889.07) ; v1@5025.98,3894.02 5005.04,3914.96 v1(5005.04,3918.62) 5026.03,3939.62 v1(5026.03,3948.12) 5026.03,3956.68 v1(5005.04,3977.68) 5005.04,3986.18 v1(5026.03,4007.18) ; 5029,4232 5025,4228 v1(5025,4160) 5025,4115.75 v1(5005.04,4095.78) 5026.03,4074.79 v1(5026.03,4066.23) 5026.03,4057.73 v1(5005.04,4036.74) 5026.03,4015.74 v1(5026.03,4007.18) ; 5048.09,4232 v1(5070.5,4254.41) ; v1(5098.7,4007.22) v1(5026.03,4007.18) ; v1(5098.72,3884.11) v1(5098.72,3948.16) v1(5098.7,4007.22) ; v1(5215.21,4148.92) 5198.29,4132 v1(5185.5,4132) 5185.5,4102.6 v5(5260.5,4027.6) ; v4(5234.9,3982.35) 5260.5,4007.95 v5(5260.5,4027.6) ; v1(5360.01,4477.42) v1(5290.01,4477.43) 5255.01,4477.43 5220.01,4512.43 5055.52,4512.43 v2(5020.51,4477.42) 5124.35,4477.42 5142.85,4458.92 5201.51,4458.92 v1(5220.01,4477.43) 5220.01,4404.1 v1(5150.5,4334.59) 5140.51,4324.6 v1(5140.51,4294.42) v1(5195.51,4294.42) v1(5250.51,4294.42) v1(5305.51,4294.42) v1(5360.51,4294.42) 5388.08,4294.42 v1(5405.5,4277) ; v1(5479.11,3641.76) 5546.03,3641.76 v1(5560.58,3656.31) 5560.58,3814.33 v1(5537.92,3836.99) ; v1(5664.14,3973.81) 5637.33,3946.99 v1(5537.92,3946.99) v1(5537.92,3891.99) v1(5537.92,3836.99) ; HDMI.21 4482.54,3776.85 4568.15,3776.85 4664.39,3680.61 v2(4666.29,3680.61) ; v2(4666.29,3680.61) v2(4736.29,3680.61) v2(4804.99,3680.61) 4920.01,3680.61 v2(4950.62,3650) 5075.91,3650 v1(5125.49,3699.58) v1(5180.49,3699.58) v1(5235.49,3699.58) ; v1(5235.49,3699.58) 5262.32,3699.58 v1(5307.52,3654.37) 5355.31,3654.37 v1(5537.92,3836.99) ; v1(5235.49,3699.58) 5338.8,3802.89 v1(5338.8,3857.74) 5375.5,3894.44 v1(5375.5,3902) 5375.5,3932.24 v4(5305.74,4002) 5280.14,4027.6 v5(5260.5,4027.6)
  Inner1 w10: HDMI.22 HDMI.20 ; 5029,4232 5048.09,4232 5078.09,4232 v1(5140.51,4294.42)
  other v1: 5295,3890 4680.02,4007.2 5664.14,4021.06 5664.14,4068.3 5664.14,4115.55
HDMI0+: HDMI.7 U1.10 U1.29 U6.D1 | length 740.5
  Top Layer w4.3: HDMI.7 4565.44,4017.02 4579.96,4031.54 4680.03,4031.54 4694.56,4017.01 U1.29 4766.23,4017.01 4780.76,4031.54 4920.29,4031.58 4934.82,4017.05 U1.10 5006.49,4017.05 5021.02,4031.58 5057.77,4031.58 cw(c5057.77,4026.58) 5062.77,4026.58 5062.77,4024.5 ccw(c5067.77,4024.5) 5072.77,4024.5 5072.77,4026.58 cw(c5077.77,4026.58) 5082.77,4026.58 5082.77,4024.5 ccw(c5087.77,4024.5) 5092.77,4024.5 5092.77,4026.58 cw(c5097.77,4026.58) 5097.77,4031.58 5121.91,4031.58 5138.69,4014.8 U6.D1
HDMI0-: HDMI.9 U1.12 U1.27 U6.D2 | length 741.8
  Top Layer w4.3: HDMI.9 4565.44,4056.39 4580,4041.84 4680.02,4041.84 4694.55,4056.38 U1.27 ; U1.27 4766.23,4056.38 4780.76,4041.84 4920.29,4041.88 4934.82,4056.41 U1.12 5006.5,4056.41 5021.03,4041.88 5126.18,4041.88 5140.07,4027.98 5187.89,4027.98 5196.52,4019.36 U6.D2
HDMI1+: HDMI.4 U1.7 U1.32 U6.E1 | length 742.2
  Top Layer w4.3: HDMI.4 4565.44,3957.96 4579.96,3972.48 4680.03,3972.48 4694.56,3957.95 4736.34,3957.95 4766.23,3957.95 4780.76,3972.48 4920.29,3972.52 4934.82,3957.99 U1.7 5006.5,3957.99 5021.03,3972.53 5055.89,3972.53 cw(c5055.89,3967.53) 5060.89,3967.53 5060.89,3965 ccw(c5065.89,3965) 5070.89,3965 5070.89,3967.53 cw(c5075.89,3967.53) 5080.89,3967.53 5080.89,3965 ccw(c5085.89,3965) 5090.89,3965 5090.89,3967.53 cw(c5095.89,3967.53) 5095.89,3972.53 5123.04,3972.53 5139.71,3989.2 U6.E1
HDMI1-: HDMI.6 U1.9 U1.30 U6.E2 | length 740.9
  Top Layer w4.3: HDMI.6 4565.44,3997.33 4580,3982.78 4680.02,3982.78 4694.55,3997.32 U1.30 4766.23,3997.32 4780.76,3982.78 4920.29,3982.82 4934.82,3997.36 U1.9 5006.49,3997.36 5021.02,3982.83 5118.77,3982.83 5137.55,4001.61 5184.11,4001.61 U6.E2
HDMI2+: HDMI.1 U1.4 U1.35 U6.F1 | length 759.8
  Top Layer w4.3: HDMI.1 4565.44,3898.91 4579.96,3913.43 4680.03,3913.43 4694.56,3898.89 U1.35 4766.23,3898.89 4780.76,3913.43 4920.29,3913.47 4934.82,3898.93 U1.4 5006.49,3898.93 5021.02,3913.47 5056.91,3913.47 cw(c5056.91,3908.47) 5061.91,3908.47 5061.91,3905 ccw(c5066.91,3905) 5071.91,3905 5071.91,3908.47 cw(c5076.91,3908.47) 5081.91,3908.47 5081.91,3905 ccw(c5086.91,3905) 5091.91,3905 5091.91,3908.47 cw(c5096.91,3908.47) 5096.91,3913.47 5103.04,3913.47 5153.18,3963.61 U6.F1
HDMI2-: HDMI.3 U1.6 U1.33 U6.F2 | length 757.4
  Top Layer w4.3: HDMI.3 4565.44,3938.28 4580,3923.73 4680.02,3923.73 4694.55,3938.26 U1.33 4766.23,3938.26 4780.76,3923.73 4920.29,3923.77 4934.82,3938.3 U1.6 5006.5,3938.3 5021.03,3923.77 5098.77,3923.77 5151.02,3976.02 5188.67,3976.02 5196.52,3968.17 U6.F2
HDMI5V: C19.2 HDMI.18 R16.1 R17.1 U1.38 | length 767.1
  Top Layer w11.8: HDMI.18 4563.85,4233.56 v1(4568.98,4238.7) 4574.94,4244.66 R16.1 R17.1@4675,4244.66 ; C19.2 4695.44,3822.12 v1(4695.44,3830.56) 4704.73,3839.84 U1.38
  Bottom Layer w20: v1(4568.98,4238.7) 4597.27,4238.7 4625,4210.97 4625,3901 v1(4695.44,3830.56)
HDMICEC: R12.2 U1.16 U6.G1 | length 760.8
  Top Layer w5: v1(5154.39,3922.43) 5169.98,3938.02 U6.G1
  Top Layer w10: v1(4895,4430.47) R12.2@4895,4480.31
  Top Layer w11.8: U1.16 v1(5005.04,4135.15)
  Bottom Layer w5: v1(4895,4430.47) 4940,4385.46 4940,4220 5005.04,4154.96 v1(5005.04,4135.15) 5059.85,4135.15 5154.39,4040.61 v1(5154.39,3922.43)
HDMICEC_OUT: HDMI.13 U1.23 | length 237.6
  Top Layer w4.3: HDMI.13 U1.23@4736.29,4135.13
HDMICLK+: HDMI.10 U1.13 U1.26 U6.C1 | length 754.6
  Top Layer w4.3: HDMI.10 4565.44,4076.07 4579.96,4090.59 4680.03,4090.59 4694.56,4076.05 U1.26 4766.23,4076.05 4780.76,4090.59 4920.29,4090.63 4934.82,4076.09 U1.13 5006.5,4076.11 5021.03,4090.64 5056.22,4090.64 cw(c5056.22,4085.64) 5061.22,4085.64 5061.22,4083.5 ccw(c5066.22,4083.5) 5071.22,4083.5 5071.22,4085.64 cw(c5076.22,4085.64) 5081.22,4085.64 5081.22,4083.5 ccw(c5086.22,4083.5) 5091.22,4083.5 5091.22,4085.64 cw(c5096.22,4085.64) 5096.22,4090.64 5114.16,4090.64 5164.41,4040.39 U6.C1
HDMICLK-: HDMI.12 U1.15 U1.24 U6.C2 | length 753
  Top Layer w4.3: HDMI.12 4565.44,4115.44 4580,4100.89 4680.02,4100.89 4694.55,4115.43 U1.24 ; U1.24 4766.23,4115.43 4780.76,4100.89 4920.29,4100.93 4934.82,4115.47 U1.15 ; U1.15 5006.49,4115.48 5021.02,4100.94 5118.43,4100.94 5165.79,4053.57 5183.34,4053.57 U6.C2
HDMIHPD: R15.2 U1.19 U6.H2 | length 775.4
  Top Layer w5: v1(5184.99,3883.42) 5184.99,3888.49 5196.52,3900.02 U6.H2
  Top Layer w10: v1(4955.28,4430.47) R15.2@4955.28,4480.31
  Top Layer w11.8: U1.19 v1(5005.04,4194.22)
  Bottom Layer w5: v1(4955.28,4430.47) 4955.28,4243.98 v1(5005.04,4194.22) 5020.78,4194.22 5170,4045 5170,3898.41 v1(5184.99,3883.42)
HDMIHPD_OUT: HDMI.19 R13.2 U1.20 | length 310.4
  Top Layer w11.8: HDMI.19 4553.24,4253.24 4580,4280 4695,4280 4736.35,4238.65 U1.20
HDMISCL: R2.2 U1.17 U6.H3 | length 786.9
  Top Layer w5: v1(5207.1,3845) 5207.1,3859.1 5212.1,3864.1 5212.1,3882.1 5222.11,3892.11 U6.H3
  Top Layer w10: v1(5050,3829.81) 5060,3819.81 R2.2
  Top Layer w11.8: v1(4914.39,4154.85) U1.17
  Bottom Layer w5: v1(4914.39,4154.85) 4950,4119.24 4950,3840 4980,3810 5030.19,3810 v1(5050,3829.81) 5191.91,3829.81 v1(5207.1,3845)
HDMISCL_OUT: HDMI.15 R16.2 U1.22 | length 254.8
  Top Layer w11.8: HDMI.15 4579.5,4174.5 4590.34,4185.34 R16.2 4640.52,4154.81 U1.22
HDMISDA: R3.2 U1.18 U6.G3 | length 768.1
  Top Layer w5: v1(5184.99,3850) 5200.29,3865.3 5200.29,3887.79 5209.31,3896.81 5209.31,3925.22 U6.G3
  Top Layer w10: R3.2 5000,3819.81 v1(5010,3829.81)
  Top Layer w11.8: v1(4924.39,4174.52) U1.18
  Bottom Layer w5: v1(4924.39,4174.52) 4965,4133.92 4965,3855 4990.19,3829.81 v1(5010,3829.81) 5024.81,3829.81 5045,3850 v1(5184.99,3850)
HDMISDA_OUT: HDMI.16 R17.2 U1.21 | length 263
  Top Layer w11.8: HDMI.16 4570.75,4194.19 4591.55,4215 4630,4215 4660,4185 4690,4185 4700.47,4174.53 U1.21
HOST_SCL: CN1.8 R9.2 U6.H4 | length 1368.3
  Top Layer w5: v1(5237.7,3852) 5237.7,3869.2 5247.7,3879.2 U6.H4
  Top Layer w8: v1(5583.41,4171.68) 5590.26,4178.54 CN1.8@5652.06,4178.54
  Top Layer w10: v1(5335.51,3557.57) 5368.72,3557.57 R9.2@5378.72,3567.57
  Bottom Layer w5: v1(5237.7,3852) 5237.7,3802.3 5290,3750 5290,3590 5322.43,3557.57 v1(5335.51,3557.57) 5362.57,3557.57 5390,3585 5570,3585 5588.41,3603.41 5588.41,4166.68 v1(5583.41,4171.68)
HOST_SDA: CN1.6 R10.2 U6.G4 | length 1239.1
  Top Layer w5: U6.G4 5247.7,3933.02 5260.5,3920.22 5260.5,3864.5 5265.5,3859.5 v1(5265.5,3847)
  Top Layer w8: v1(5583.41,4201.14) 5590.26,4194.29 CN1.6@5652.06,4194.29
  Top Layer w10: R10.2@5544.84,3567.57 5550.05,3572.78 v1(5550.05,3603.57)
  Bottom Layer w5: v1(5265.5,3847) 5265.5,3829.5 5491.43,3603.57 v1(5550.05,3603.57) 5568.57,3603.57 5575.88,3610.88 5575.88,4139.12 5560,4155 5560,4177.73 v1(5583.41,4201.14)
pads on no net: CN1.1 CN1.3 CN1.5 CN1.7 CN1.9 CN1.11 CN1.13 CN1.15 CN1.17 CN1.19 CN1.21 CN1.23 CN1.25 CN1.27 CN1.29 CN1.31 CN1.33 CN1.35 CN1.37 CN1.39 HDMI.14 U3.4 U6.A5 U6.B3 U6.B4 U6.F7 U6.F8 U6.G6 U6.G7 U6.G8 U6.H1 U6.H6 U7.6
copper on no net: | length 1014.2
  Top Layer w5: v1(5154.39,3896.84) 5169.98,3912.43 5170.93,3912.43
  Bottom Layer w5: v1(5154.39,3896.84) 5155,3896.23 5155,3885 5171.88,3868.12 5298.12,3868.12 5550,4120 5550,4275 5580,4305 5580,4545 5555,4570

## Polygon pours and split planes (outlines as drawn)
GND on Bottom Layer (solid, remove dead copper, pour order 14): 3000,5335 6545,5335 6545,3000 3000,3000
GND on Inner1 (solid, remove dead copper): 3100,5120 6845,5120 6845,3050 3100,3050
GND on Top Layer (solid, remove dead copper, pour order 12): 3145,5085 6485,5085 6485,3160 3145,3160
3V3 on Inner2 (solid, remove dead copper): 5764.21,4312.5 5469.21,4607.5 5327.5,4607.5 5682.5,4252.5 5682.5,3947.5 5585,3850 5460,3850 5395,3785 5233.16,3785 5220.16,3772 5220.16,3724.93 5235.5,3709.59 5268.55,3709.59 5307.52,3670.62 5555.62,3670.62 5764.21,3879.21
3V3 on Top Layer (solid, remove dead copper, pour order 0): 4794.44,4455.42 4835.53,4455.42 4842.56,4462.45 4842.56,4493.95 4830.37,4506.14 4830.37,4506.15 4798.87,4506.15 4769.86,4477.13 4746.7,4477.13 4746.7,4465.13 4768.99,4465.13 4769.99,4464.13 4784.82,4464.13
A3V3 on Inner2 (solid, remove dead copper): 4872.55,4265 4937.55,4200 5081.97,4200 5136.12,4145.85 5136.12,3694.45 5160.57,3670 5255.57,3670 5305.57,3620 5010,3620 4795,3835 4795,4205.46 4854.54,4265
3V3 on Top Layer (solid, remove dead copper, pour order 2): 4842.56,4464.35 4842.56,4555.12 4830.37,4567.32 4797.7,4567.32 4785.51,4555.13 4785.51,4464.35
$1N34238 on Top Layer (solid, remove dead copper, pour order 4): 4712.7,4465.13 4712.7,4500.13 4737.7,4525.13 4737.7,4595.13 4732.7,4600.13 4678.95,4600.13 4674.61,4595.79 4674.61,4503.22 4682.7,4495.13 4682.7,4470.13 4687.7,4465.13
3V3 on Inner2 (solid, remove dead copper): 5235.54,3709.59 5330.14,3615 5430.63,3615 5514.05,3698.43 5427.48,3785 5233.16,3785 5220.16,3772 5220.16,3724.93 5235.5,3709.59 5235.5,3709.55
1V2 on Top Layer (solid, remove dead copper, pour order 6): 4662.7,4595.13 4657.7,4600.13 4607.7,4600.13 4602.7,4595.13 4602.7,4505.13 4592.7,4495.13 4542.7,4495.13 4542.7,4430.13 4652.7,4430.13 4662.7,4440.13
3V3 on Inner2 (solid, remove dead copper): 4785.51,4610 5436.71,4610 5529.21,4517.5 4866.12,4517.5 4857.56,4508.95 4785.51,4508.95
1V2 on Top Layer (solid, remove dead copper, pour order 8): 4594.03,4495.13 4594.03,4430.47 4593.7,4430.13 4537.7,4430.13 4527.7,4440.13 4527.7,4485.13 4537.7,4495.13
3V3 on Top Layer (solid, remove dead copper, pour order 10): 5601.93,4204.22 5656.93,4204.22 5659.93,4207.22 5659.93,4282.22 5656.93,4285.22 5601.93,4285.22 5598.93,4282.22 5598.93,4207.22
3V3 on Inner2 (solid, remove dead copper): 4816.06,4610 4490,4610 4485,4605 4485,4595 4490,4590 4770,4590 4790,4570 4816.06,4596.06
3V3 on Inner2 (solid, remove dead copper): 5605,4335 5612.01,4327.99 5612.01,4242.99 5625,4230 5710,4230 5715,4235 5615,4335
1V2 on Inner2 (solid, remove dead copper): 4522.7,4495.13 4512.7,4485.13 4512.7,4440.13 4522.7,4430.13 4630.68,4430.13 4743.37,4317.44 5028.38,4317.44 5112.78,4233.03 5575.5,4233.03 5575.5,4328.03 5463.53,4440 4864.6,4440 4809.47,4495.13
1V2 on Inner2 (solid, remove dead copper): 5575.5,4233.03 5575.5,3985.5 5385,3795 5225,3795 5190,3760 5174.25,3760 5164.25,3770 5164.25,3795.59 5198.66,3830 5333.02,3830 5410.77,3907.76 5410.77,4022.55 5495.27,4107.05 5495.27,4194.3 5483.6,4205.97 5360.79,4205.97 5344.75,4222 5344.75,4239.75 5365,4260 5548.53,4260
1V2 on Inner2 (solid, remove dead copper): 4864.6,4440 5115.03,4440 5134.76,4459.73 5134.76,4489.76 5140,4495 5160,4495 5165,4490 5165,4460.98 5195.71,4430.27 5170.43,4405 4899.6,4405
A3V3 on Inner2 (solid, remove dead copper): 5005.21,3669.79 4968.27,3706.72 4538.41,3706.72 4525.87,3719.26 4525.87,3730.11 4564.39,3768.62 4728.62,3768.62 4795,3835 4795,3871.3 4861.63,3871.3 5005.21,3727.71
3V3 on Inner2 (solid, remove dead copper): 5323.17,3646.97 5378.03,3646.97 5395,3630 5305,3540 4445,3540 4415,3570 4415,3587.53 4439.74,3612.28 5302.27,3612.28 5323.17,3633.17

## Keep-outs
Top Layer:
  region: 5573.54,4147.05 5628.58,4147.05 5628.58,3945.05 5573.54,3945.05
Inner2:
  region: 4925,4200 4905,4180 4905,3879.57 4970,3814.57 5056.69,3814.57 5056.69,4168.31 5025,4200
Board Outline Layer:
  lines w10: 4140,3643.11 ccw(c4258.11,3643.11) 4258.11,3525 5714.8,3525 ccw(c5714.8,3643.11) 5832.91,3643.11 5832.91,4509.25 ccw(c5714.8,4509.25) 5714.8,4627.36 4258.11,4627.36 ccw(c4258.11,4509.25) 4140,4509.25 4140,3643.11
